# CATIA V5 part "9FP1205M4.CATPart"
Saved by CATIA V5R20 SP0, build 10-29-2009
Part number: 9FP1205M4
Revision: ANY
Definition: UNKNOWN
Nomenclature: 9FP1205M4
Source: Unknown
Bounding box of the stored display mesh (mm): x -5.752 to 5.752, y 0 to 5, z -5.9 to 5.9
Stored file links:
  C:\Users\Utente\Desktop\IO LAVORO\3D X SITO CF\CUMSA\3D files PW\pw060830\pw060830_ejection\9FP1205M4.CATPart
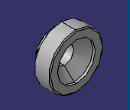
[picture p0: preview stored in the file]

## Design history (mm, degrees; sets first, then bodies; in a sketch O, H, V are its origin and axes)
Body1 "Redondeo2" (main body)
  Solid1: solid without history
